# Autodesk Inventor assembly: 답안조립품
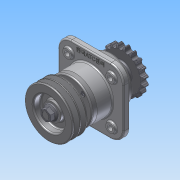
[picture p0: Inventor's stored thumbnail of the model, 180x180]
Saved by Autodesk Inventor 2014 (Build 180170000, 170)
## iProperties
Created: 2015-09
Part Number: 답안조립품
Document SubType Name: Assembly
Designer: study
Author: study
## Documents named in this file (12)
- C:\Users\study\Desktop\450909V1021\답안조립품.iam
- C:\Users\study\Desktop\450909V1021\1-본체.ipt
- C:\Users\study\Desktop\450909V1021\3-축.ipt
- C:\Users\study\Desktop\450909V1021\6-베어링 6206.ipt
- C:\Users\study\Desktop\450909V1021\7-부시.ipt
- C:\Users\study\Desktop\450909V1021\11-키 6x6.ipt
- C:\Users\study\Desktop\450909V1021\2-커버.ipt
- C:\Users\study\Desktop\450909V1021\8-오일실 30x42.ipt
- C:\Users\study\Desktop\450909V1021\10-M6.ipt
- C:\Users\study\Desktop\450909V1021\4-V벨트풀리.ipt
- C:\Users\study\Desktop\450909V1021\5-체인 스프로킷.ipt
- C:\Users\study\Desktop\450909V1021\9-M16-너트.ipt
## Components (23 placed, 11 different names)
1. 1-본체:1
2. 3-축:1 — 각도:1, 각도:2, 각도:5, 각도:6
3. 6-베어링 6206:1
4. 7-부시:1
5. 11-키 6x6:1 — 각도:1, 각도:4
6. 6-베어링 6206:2
7. 11-키 6x6:2 — 각도:2, 각도:3
8. 2-커버:1
9. 8-8-오일실 30x42:1
10. 2-커버:2
11. 8-8-오일실 30x42:2
12. 4-V벨트풀리:1 — 각도:4
13. 5-체인 스프로킷:1 — 각도:3
14. 9-M16 너트:1 — 각도:5
15. 9-M16 너트:2 — 각도:6
16. 10-M6:2
17. 10-M6:3
18. 10-M6:4
19. 10-M6:5
20. 10-M6:1
21. 10-M6:6
22. 10-M6:7
23. 10-M6:8
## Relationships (6: Angle 6)
- 각도:1 [Angle]: 3-축:1 ↔ 11-키 6x6:1
- 각도:2 [Angle]: 3-축:1 ↔ 11-키 6x6:2
- 각도:3 [Angle]: 11-키 6x6:2 ↔ 5-체인 스프로킷:1
- 각도:4 [Angle]: 11-키 6x6:1 ↔ 4-V벨트풀리:1
- 각도:5 [Angle]: 3-축:1 ↔ 9-M16 너트:1
- 각도:6 [Angle]: 3-축:1 ↔ 9-M16 너트:2
